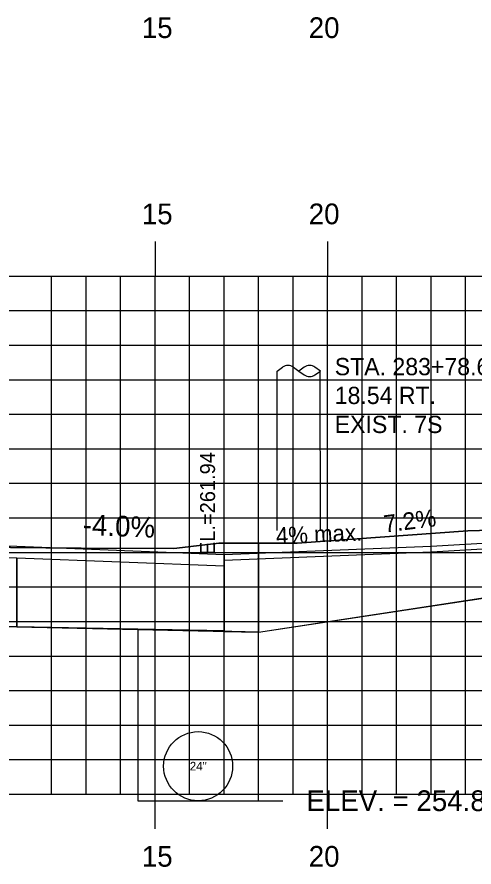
# Model space of a CAD drawing. Extents: x 856235 to 856405, y 366268 to 366378.
# Drawn here: x 856328.78 to 856342.02, y 366298.78 to 366323.39 of the extents above; entities that cross this region are included whole.
import ezdxf

# ---------------------------------------------------------------- set-up
doc = ezdxf.new("R2010")
doc.units = 0
for name, color, linetype in [('ANNOTATION', 7, 'Continuous'), ('D_Roadway_Drive_Gravel_RT', 7, 'Continuous'), ('D_Roadway_Drive_SubGrade', 7, 'Continuous'), ('D_Roadway_Edge_Shoulder', 7, 'Continuous'), ('D_Roadway_SubGrade', 7, 'Continuous'), ('D_Text_Monospaced', 7, 'Continuous'), ('D_Text_Standard', 7, 'Continuous'), ('H_V ANNOTATION', 7, 'Continuous'), ('JUNK COM EXC', 7, 'Continuous'), ('junk strct exc', 7, 'Continuous'), ('MAJOR', 7, 'Continuous'), ('MINOR', 7, 'Continuous'), ('PDRAIN', 7, 'Continuous'), ('S_Roadway_Centerline', 7, 'Continuous'), ('S_Utilities_Pole_Power', 7, 'Continuous')]:
    doc.layers.add(name, color=color, linetype=linetype)

msp = doc.modelspace()

# ---------------------------------------------------------------- linework, layer by layer
at = {"layer": 'D_Roadway_Drive_Gravel_RT'}
for p, q in [((856340.78, 366308.074), (856353.683, 366308.849)), ((856340.79, 366307.908), (856353.683, 366308.682)), ((856334.78, 366307.834), (856340.78, 366308.074)), ((856334.781, 366307.668), (856340.787, 366307.908))]:
    msp.add_line(p, q, dxfattribs=at)
at = {"layer": 'D_Roadway_Drive_SubGrade'}
for p, q in [((856335.78, 366305.586), (856346.781, 366307.266)), ((856334.78, 366305.606), (856335.78, 366305.586))]:
    msp.add_line(p, q, dxfattribs=at)
at = {"layer": 'D_Roadway_Edge_Shoulder'}
msp.add_line((856334.78, 366307.834), (856334.781, 366307.5), dxfattribs=at)
msp.add_lwpolyline([(856302.781, 366307.914), (856306.781, 366308.074), (856317.781, 366308.294), (856328.781, 366308.074), (856334.78, 366307.834)], dxfattribs=at)
at = {"layer": 'D_Roadway_SubGrade'}
for points in [[(856306.781, 366305.74), (856306.781, 366307.74), (856317.781, 366307.96), (856328.781, 366307.74), (856328.781, 366305.74), (856317.781, 366305.96)], [(856328.781, 366307.74), (856334.781, 366307.5), (856334.781, 366305.62), (856328.781, 366305.74)]]:
    msp.add_lwpolyline(points, close=True, dxfattribs=at)
at = {"layer": 'D_Text_Standard'}
msp.add_lwpolyline([(856335.78, 366300.703), (856335.806, 366300.703), (856336.486, 366300.703)], dxfattribs=at)
at = {"layer": 'JUNK COM EXC'}
for points in [[(856335.781, 366308.158), (856335.781, 366305.586), (856347.021, 366307.28), (856353.683, 366307.68), (856353.683, 366308.849), (856353.214, 366308.843), (856341.841, 366308.513), (856336.902, 366308.157), (856335.781, 366308.158)], [(856291.781, 366306.632), (856301.781, 366305.64), (856306.781, 366305.74), (856317.781, 366305.96), (856328.781, 366305.74), (856335.78, 366305.586), (856335.781, 366308.158), (856334.63, 366308.158), (856333.411, 366308.015), (856333.315, 366308.002), (856330.64, 366308.017), (856328.588, 366308.036), (856325.349, 366308.101), (856317.731, 366308.235), (856314.412, 366308.118), (856307.504, 366307.852), (856302.732, 366307.68), (856301.781, 366307.634)]]:
    msp.add_lwpolyline(points, dxfattribs=at)
at = {"layer": 'junk strct exc'}
msp.add_lwpolyline([(856332.28, 366305.67), (856332.28, 366300.703), (856335.78, 366300.703), (856335.78, 366305.586)], close=True, dxfattribs=at)
at = {"layer": 'MAJOR'}
for p, q in [((856332.781, 366316.895), (856332.781, 366315.893)), ((856337.781, 366316.895), (856337.781, 366315.893)), ((856247.781, 366315.893), (856387.781, 366315.893)), ((856247.781, 366315.893), (856387.781, 366315.893)), ((856332.781, 366300.893), (856332.781, 366315.893)), ((856337.781, 366300.893), (856337.781, 366315.893)), ((856247.781, 366310.893), (856387.781, 366310.893)), ((856247.781, 366305.893), (856387.781, 366305.893)), ((856247.781, 366300.893), (856387.781, 366300.893)), ((856247.781, 366300.893), (856387.781, 366300.893)), ((856332.781, 366299.891), (856332.781, 366300.893)), ((856337.781, 366299.891), (856337.781, 366300.893))]:
    msp.add_line(p, q, dxfattribs=at)
at = {"layer": 'MINOR'}
for p, q in [((856329.781, 366300.893), (856329.781, 366315.893)), ((856330.781, 366300.893), (856330.781, 366315.893)), ((856331.781, 366300.893), (856331.781, 366315.893)), ((856333.781, 366300.893), (856333.781, 366315.893)), ((856334.781, 366300.893), (856334.781, 366315.893)), ((856335.781, 366300.893), (856335.781, 366315.893)), ((856336.781, 366300.893), (856336.781, 366315.893)), ((856338.781, 366300.893), (856338.781, 366315.893)), ((856339.781, 366300.893), (856339.781, 366315.893)), ((856340.781, 366300.893), (856340.781, 366315.893)), ((856341.781, 366300.893), (856341.781, 366315.893)), ((856247.781, 366314.893), (856387.781, 366314.893)), ((856247.781, 366313.893), (856387.781, 366313.893)), ((856247.781, 366312.893), (856387.781, 366312.893)), ((856247.781, 366311.893), (856387.781, 366311.893)), ((856247.781, 366309.893), (856387.781, 366309.893)), ((856247.781, 366308.893), (856387.781, 366308.893)), ((856247.781, 366307.893), (856387.781, 366307.893)), ((856247.781, 366306.893), (856387.781, 366306.893)), ((856247.781, 366304.893), (856387.781, 366304.893)), ((856247.781, 366303.893), (856387.781, 366303.893)), ((856247.781, 366302.893), (856387.781, 366302.893)), ((856247.781, 366301.893), (856387.781, 366301.893))]:
    msp.add_line(p, q, dxfattribs=at)
at = {"layer": 'PDRAIN'}
msp.add_lwpolyline([(856332.28, 366305.67), (856332.28, 366300.703), (856335.78, 366300.703), (856335.78, 366305.586)], dxfattribs=at)
msp.add_circle((856334.03, 366301.703), 1, dxfattribs=at)
at = {"layer": 'S_Roadway_Centerline'}
msp.add_lwpolyline([(856288.766, 366307.134), (856291.997, 366307.346), (856293.116, 366307.459), (856296.849, 366307.753), (856299.153, 366307.782), (856300.226, 366307.769), (856300.611, 366307.582), (856300.668, 366307.591), (856300.837, 366307.587), (856302.732, 366307.68), (856307.504, 366307.852), (856314.412, 366308.118), (856317.731, 366308.235), (856325.349, 366308.101), (856328.588, 366308.036), (856330.64, 366308.017), (856333.315, 366308.002), (856333.411, 366308.015), (856334.63, 366308.158), (856336.902, 366308.157), (856341.841, 366308.513), (856353.214, 366308.843), (856361.49, 366308.945)], dxfattribs=at)
at = {"layer": 'S_Utilities_Pole_Power'}
for p, q in [((856336.321, 366308.524), (856336.318, 366313.143)), ((856336.321, 366313.143), (856336.478, 366313.253)), ((856336.79, 366313.253), (856336.946, 366313.143)), ((856337.103, 366313.253), (856336.946, 366313.143)), ((856336.946, 366313.143), (856337.103, 366313.032)), ((856337.571, 366313.143), (856337.415, 366313.253)), ((856337.415, 366313.032), (856337.571, 366313.143)), ((856337.571, 366308.524), (856337.568, 366313.143))]:
    msp.add_line(p, q, dxfattribs=at)
for centre, start, end in [((856336.634, 366313.033), 90, 125.2644), ((856336.634, 366313.033), 54.7356, 90), ((856337.259, 366313.033), 90, 125.2644), ((856337.259, 366313.033), 54.7356, 90), ((856337.259, 366313.254), 234.7356, 270), ((856337.259, 366313.254), 270, 305.2644)]:
    msp.add_arc(centre, 0.271, start, end, dxfattribs=at)

# ---------------------------------------------------------------- texts
at = {"layer": 'ANNOTATION'}
msp.add_text('-4.0%', height=0.6, rotation=357.7094, dxfattribs=at).set_placement((856330.677, 366308.399))
at = {"layer": 'D_Roadway_Drive_Gravel_RT'}
msp.add_text('4% max.', height=0.48, rotation=2.2906, dxfattribs=at).set_placement((856336.293, 366308.135))
at = {"layer": 'D_Text_Monospaced'}
for s, height, p in [('STA. 283+78.68', 0.49998, (856337.988, 366313.022)), ('18.54 RT.', 0.5, (856337.988, 366312.188)), ('EXIST. 7S', 0.5, (856337.988, 366311.348))]:
    msp.add_text(s, height=height, dxfattribs=at).set_placement(p)
msp.add_text('7.2%', height=0.5, rotation=7.0925, dxfattribs=at).set_placement((856339.437, 366308.465))
at = {"layer": 'D_Text_Standard'}
msp.add_text(' EL.=261.94', height=0.4335, rotation=90, dxfattribs=at).set_placement((856334.52, 366307.654))
msp.add_text('ELEV. = 254.81', height=0.6, dxfattribs=at).set_placement((856337.166, 366300.403))
at = {"layer": 'H_V ANNOTATION'}
for s, p in [('15', (856332.398, 366322.785)), ('20', (856337.235, 366322.785)), ('15', (856332.398, 366317.393)), ('20', (856337.235, 366317.393)), ('15', (856332.398, 366298.793)), ('20', (856337.235, 366298.793))]:
    msp.add_text(s, height=0.6, dxfattribs=at).set_placement(p)
at = {"layer": 'PDRAIN'}
msp.add_text('24"', height=0.25, dxfattribs=at).set_placement((856333.788, 366301.578))

doc.saveas('drawing.dxf')
